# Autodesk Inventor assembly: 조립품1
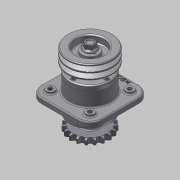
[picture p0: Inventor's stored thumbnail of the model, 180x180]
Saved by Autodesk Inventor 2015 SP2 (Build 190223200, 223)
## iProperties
Created: 2015-07
Part Number: 조립품1
Document SubType Name: Assembly
Designer: AMC
Author: AMC
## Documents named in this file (12)
- C:\Users\AMC\Desktop\450735V1006\조립품1.iam
- C:\Users\AMC\Desktop\450735V1006\본체.ipt
- C:\Users\AMC\Desktop\450735V1006\2-커버.ipt
- C:\Users\AMC\Desktop\450735V1006\3-축.ipt
- C:\Users\AMC\Desktop\450735V1006\4-V벨트풀리.ipt
- C:\Users\AMC\Desktop\450735V1006\5-체인 스프로킷.ipt
- C:\Users\AMC\Desktop\450735V1006\6-베어링 6206.ipt
- C:\Users\AMC\Desktop\450735V1006\7-부시.ipt
- C:\Users\AMC\Desktop\450735V1006\8-오일실 30x42.ipt
- C:\Users\AMC\Desktop\450735V1006\9-M16-너트.ipt
- C:\Users\AMC\Desktop\450735V1006\10-M6.ipt
- C:\Users\AMC\Desktop\450735V1006\11-키 6x6.ipt
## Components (23 placed, 10 different names)
1. 2-커버:1
2. 3-축:1
3. 4-V벨트풀리:1
4. 5-체인 스프로킷:1
5. 6-베어링 6206:1
6. 7-부시:1
7. 8-8-오일실 30x42:1
8. 9-M16 너트:1
9. 10-M6:1
10. 11-키 6x6:1
11. 6-베어링 6206:2
12. 2-커버:2
13. 8-8-오일실 30x42:2
14. 11-키 6x6:2
15. 9-M16 너트:2
16. 10-M6:2
17. 10-M6:3
18. 10-M6:4
19. 10-M6:5
20. 10-M6:6
21. 10-M6:7
22. 10-M6:8
23. 10-M6:9
